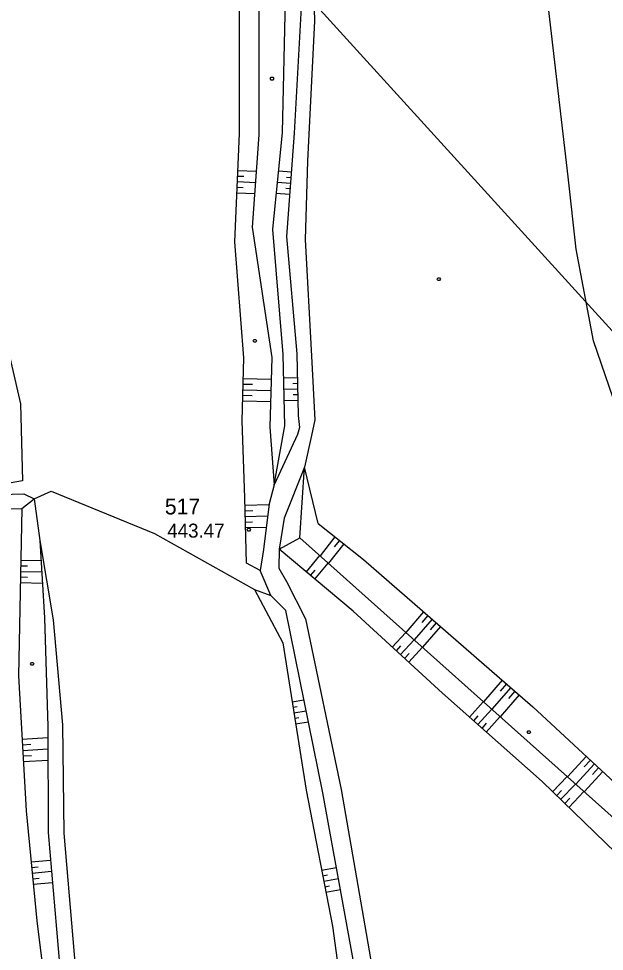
# Model space of a CAD drawing. Extents: x -664960 to -662754, y -993849 to -991145.
# Drawn here: x -663855.3 to -663729.8, y -993173.7 to -992973.8 of the extents above; entities that cross this region are included whole.
import ezdxf

# ---------------------------------------------------------------- set-up
doc = ezdxf.new("R2010")
doc.units = 0
for name, color, linetype in [('Vrstva 1', 7, 'Continuous'), ('Vrstva 13', 7, 'Continuous'), ('Vrstva 27', 7, 'Continuous'), ('Vrstva 57', 7, 'Continuous'), ('Vrstva 63', 7, 'Continuous'), ('Vrstva 8', 7, 'Continuous')]:
    doc.layers.add(name, color=color, linetype=linetype)

msp = doc.modelspace()

# ---------------------------------------------------------------- linework, layer by layer
at = {"layer": 'Vrstva 13'}
for points in [[(-663800.828, -992986.314), (-663800.648, -992986.614), (-663800.828, -992986.914), (-663801.188, -992986.914), (-663801.368, -992986.614), (-663801.188, -992986.314), (-663800.828, -992986.314)], [(-663765.08, -993029.301), (-663764.9, -993029.601), (-663765.08, -993029.901), (-663765.44, -993029.901), (-663765.62, -993029.601), (-663765.44, -993029.301), (-663765.08, -993029.301)], [(-663804.509, -993042.536), (-663804.329, -993042.836), (-663804.509, -993043.136), (-663804.869, -993043.136), (-663805.049, -993042.836), (-663804.869, -993042.536), (-663804.509, -993042.536)], [(-663852.233, -993111.799), (-663852.053, -993112.099), (-663852.233, -993112.399), (-663852.593, -993112.399), (-663852.773, -993112.099), (-663852.593, -993111.799), (-663852.233, -993111.799)], [(-663745.745, -993126.418), (-663745.565, -993126.718), (-663745.745, -993127.018), (-663746.105, -993127.018), (-663746.285, -993126.718), (-663746.105, -993126.418), (-663745.745, -993126.418)]]:
    msp.add_lwpolyline(points, dxfattribs=at)
at = {"layer": 'Vrstva 27'}
msp.add_line((-663804.75, -993096.16), (-663801.24, -993097.47), dxfattribs=at)
for points in [[(-663798.66, -992907.21), (-663803.28, -992878.12), (-663800.21, -992877.55), (-663794.6, -992912.25), (-663792.62, -992948.5), (-663791.93, -992974.25), (-663793.37, -993004.29), (-663793.87, -993021.14), (-663792.51, -993046.15), (-663791.85, -993059.78), (-663792.52, -993063.11), (-663794.05, -993069.95), (-663798.39, -993080.84), (-663799.49, -993087.48), (-663799.56, -993091.56)], [(-663798.66, -992907.21), (-663796.38, -992936.7), (-663794.84, -992972.55), (-663796.22, -992998.34), (-663797.91, -993020.49), (-663795.68, -993045.6), (-663795.37, -993058.81), (-663795.1, -993061.42), (-663795.54, -993062.92), (-663800.56, -993073.72), (-663801.6, -993077.75), (-663802.8, -993087.56), (-663803.57, -993092.11)], [(-663850.76, -993085.62), (-663849.8, -993102.26), (-663849.04, -993125.53), (-663849.03, -993148.28), (-663846.5, -993177.24), (-663842.24, -993200.89), (-663833.38, -993228.59), (-663823.87, -993255.25), (-663817.2, -993274.88), (-663813.34, -993284.73), (-663801.76, -993299.65)], [(-663850.76, -993085.62), (-663847.9, -993102.66), (-663845.89, -993125.16), (-663845.65, -993148.43), (-663843.14, -993177.79), (-663839.75, -993198.46), (-663830.82, -993226.75), (-663821.82, -993253.84), (-663814.3, -993276.27), (-663807.96, -993288.1), (-663798.2, -993300.61)], [(-663566.277, -993492.747), (-663573.405, -993481.951), (-663582.75, -993464.98), (-663590.11, -993455.44), (-663603.05, -993446.17), (-663622.25, -993432.96), (-663645.5, -993416.15), (-663669.59, -993394.5), (-663684.5, -993376.48), (-663705.06, -993341.62), (-663719.09, -993320.53), (-663726.89, -993308.98), (-663732.46, -993301.67), (-663748.35, -993282.31), (-663755.36, -993267.18), (-663772.33, -993222.31), (-663780.37, -993193.12), (-663790.1, -993139.75), (-663798.05, -993100.64), (-663801.24, -993097.47), (-663803.57, -993092.11)], [(-663799.56, -993091.56), (-663797.87, -993094.45), (-663793.81, -993102.42), (-663786.19, -993139.05), (-663776.88, -993192.57), (-663768.94, -993221.33), (-663752.26, -993266.73), (-663745.33, -993280.34), (-663730.13, -993299.39), (-663724.15, -993307.36), (-663716.72, -993318.58), (-663702.35, -993340.18), (-663681.94, -993374.67), (-663667.01, -993392.3), (-663643.69, -993413.59), (-663620.3, -993430.55), (-663600.52, -993442.61), (-663587.6, -993453.58), (-663580.01, -993463.19), (-663569.843, -993479.941), (-663562.861, -993490.76)]]:
    msp.add_lwpolyline(points, dxfattribs=at)
at = {"layer": 'Vrstva 57'}
msp.add_lwpolyline([(-663998.65, -992779.1), (-663970.58, -992774.57), (-663926.29, -992822.75), (-663869.96, -992884.99), (-663795.03, -992967.03), (-663725.94, -993043.04), (-663662.36, -993113.13), (-663592.02, -993190.94), (-663529.08, -993259.82), (-663458.89, -993337.24), (-663418.62, -993381.56)], dxfattribs=at)
at = {"layer": 'Vrstva 63'}
for p, q in [((-663808.3, -993006.301), (-663804.402, -993006.469)), ((-663796.856, -993006.677), (-663799.596, -993006.468)), ((-663808.352, -993007.5), (-663807.065, -993007.556)), ((-663796.947, -993007.873), (-663797.87, -993007.803)), ((-663808.456, -993009.898), (-663807.19, -993009.952)), ((-663808.404, -993008.699), (-663804.571, -993008.864)), ((-663797.039, -993009.07), (-663799.838, -993008.856)), ((-663797.13, -993010.266), (-663798.072, -993010.194)), ((-663808.507, -993011.097), (-663804.741, -993011.259)), ((-663797.221, -993011.463), (-663800.08, -993011.245)), ((-663807.198, -993052.103), (-663805.202, -993052.152)), ((-663807.169, -993050.904), (-663801.163, -993051.05)), ((-663795.558, -993050.795), (-663798.51, -993050.864)), ((-663795.53, -993051.995), (-663796.513, -993052.018)), ((-663807.257, -993054.503), (-663805.267, -993054.551)), ((-663807.227, -993053.303), (-663801.242, -993053.449)), ((-663795.502, -993053.195), (-663798.454, -993053.264)), ((-663795.474, -993054.394), (-663796.457, -993054.417)), ((-663807.286, -993055.702), (-663801.321, -993055.848)), ((-663795.445, -993055.594), (-663798.397, -993055.663)), ((-663791.11, -993082), (-663794.05, -993069.95)), ((-663852.02, -993076.68), (-663850.76, -993085.62)), ((-663806.807, -993078.09), (-663801.628, -993077.954)), ((-663801.54, -993077.54), (-663801.54, -993077.54)), ((-663806.776, -993079.29), (-663805.116, -993079.246)), ((-663806.744, -993080.489), (-663801.958, -993080.363)), ((-663806.712, -993081.689), (-663805.184, -993081.649)), ((-663806.681, -993082.889), (-663802.289, -993082.773)), ((-663787.503, -993084.872), (-663790.717, -993088.908)), ((-663785.625, -993086.367), (-663788.924, -993090.51)), ((-663786.564, -993085.62), (-663787.648, -993086.982)), ((-663854.872, -993089.864), (-663850.51, -993089.955)), ((-663793.646, -993092.37), (-663790.735, -993088.892)), ((-663791.805, -993093.911), (-663788.945, -993090.492)), ((-663854.922, -993092.263), (-663850.371, -993092.358)), ((-663854.897, -993091.063), (-663853.413, -993091.094)), ((-663792.725, -993093.141), (-663791.765, -993091.992)), ((-663854.947, -993093.463), (-663853.4, -993093.495)), ((-663854.972, -993094.662), (-663850.233, -993094.762)), ((-663768.509, -993100.937), (-663772.334, -993105.337)), ((-663766.697, -993102.511), (-663770.544, -993106.936)), ((-663767.603, -993101.724), (-663768.88, -993103.193)), ((-663764.886, -993104.085), (-663768.754, -993108.536)), ((-663765.792, -993103.298), (-663767.076, -993104.776)), ((-663775.225, -993108.48), (-663772.334, -993105.336)), ((-663774.342, -993109.292), (-663773.375, -993108.241)), ((-663773.458, -993110.104), (-663770.544, -993106.936)), ((-663771.692, -993111.729), (-663768.755, -993108.535)), ((-663772.575, -993110.917), (-663771.601, -993109.857)), ((-663751.644, -993115.596), (-663755.67, -993120.228)), ((-663750.738, -993116.383), (-663752.082, -993117.93)), ((-663749.832, -993117.17), (-663753.88, -993121.828)), ((-663748.927, -993117.958), (-663750.278, -993119.513)), ((-663796.682, -993120.205), (-663794.153, -993119.81)), ((-663758.659, -993123.531), (-663755.701, -993120.201)), ((-663748.021, -993118.745), (-663752.091, -993123.427)), ((-663796.497, -993121.391), (-663795.637, -993121.256)), ((-663796.311, -993122.576), (-663793.675, -993122.164)), ((-663756.864, -993125.125), (-663753.911, -993121.8)), ((-663796.126, -993123.762), (-663795.23, -993123.622)), ((-663795.941, -993124.947), (-663793.196, -993124.518)), ((-663757.761, -993124.328), (-663756.777, -993123.22)), ((-663755.07, -993126.718), (-663752.122, -993123.399)), ((-663755.967, -993125.922), (-663754.985, -993124.815)), ((-663854.592, -993128.24), (-663849.039, -993127.915)), ((-663854.522, -993129.438), (-663852.696, -993129.331)), ((-663854.451, -993130.636), (-663849.038, -993130.319)), ((-663854.381, -993131.834), (-663852.602, -993131.73)), ((-663733.624, -993131.925), (-663737.684, -993136.302)), ((-663854.311, -993133.032), (-663849.037, -993132.723)), ((-663731.865, -993133.557), (-663735.894, -993137.901)), ((-663732.745, -993132.741), (-663734.091, -993134.193)), ((-663730.985, -993134.373), (-663732.322, -993135.814)), ((-663740.85, -993139.524), (-663737.712, -993136.277)), ((-663730.105, -993135.189), (-663734.104, -993139.501)), ((-663739.125, -993141.192), (-663735.921, -993137.877)), ((-663739.987, -993140.358), (-663738.931, -993139.265)), ((-663737.399, -993142.86), (-663734.13, -993139.478)), ((-663738.262, -993142.026), (-663737.184, -993140.911)), ((-663852.653, -993154.575), (-663848.514, -993154.183)), ((-663852.541, -993155.769), (-663851.165, -993155.639)), ((-663852.428, -993156.964), (-663848.305, -993156.574)), ((-663790.385, -993156.358), (-663787.185, -993155.738)), ((-663852.315, -993158.159), (-663850.945, -993158.029)), ((-663790.157, -993157.536), (-663789.096, -993157.331)), ((-663789.928, -993158.714), (-663786.755, -993158.099)), ((-663852.202, -993159.353), (-663848.097, -993158.965)), ((-663789.7, -993159.892), (-663788.648, -993159.688)), ((-663789.472, -993161.071), (-663786.324, -993160.46))]:
    msp.add_line(p, q, dxfattribs=at)
for points in [[(-663803.57, -993092.11), (-663806.48, -993090.5), (-663806.85, -993076.47), (-663807.39, -993059.97), (-663807.06, -993046.45), (-663808.96, -993021.59), (-663807.96, -992998.41), (-663807.99, -992966.75), (-663808.62, -992935.63), (-663810.18, -992908.75), (-663815.86, -992880.07), (-663824.59, -992849.12), (-663829.13, -992816.83), (-663835.46, -992781.67), (-663839.851, -992756.951)], [(-663703.12, -993141.55), (-663703.33, -993135.57), (-663706.44, -993107.61), (-663711.52, -993089.56), (-663718.92, -993074.62), (-663727.02, -993057.64), (-663732.05, -993042.86), (-663735.81, -993023.2), (-663737.53, -993007.67), (-663742.14, -992967.66), (-663747.72, -992923.84), (-663786.36, -992914.44), (-663794.6, -992912.25)], [(-663803.84, -992971.94), (-663803.85, -992998.65), (-663805.25, -993018.47), (-663801.01, -993046.38), (-663801.5, -993061.31), (-663800.56, -993073.72), (-663798.27, -993061.07), (-663798.63, -993045.77), (-663800.86, -993018.93), (-663798.75, -992998.13), (-663798.09, -992969.67)], [(-663953.96, -992976.6), (-663944.14, -992978), (-663916.87, -992989.68), (-663873.66, -993007.23), (-663861.96, -993010.62), (-663860.36, -993033.02), (-663854.94, -993056.31), (-663854.48, -993072.82), (-663862.23, -993074.18), (-663868.63, -993079.01), (-663886.15, -993085.85), (-663925.46, -993100.87), (-663931.37, -993104)], [(-663799.49, -993087.48), (-663795.01, -993085.07), (-663794.05, -993069.95)], [(-663861.8, -993075.87), (-663854.19, -993075.63), (-663852.02, -993076.68)], [(-663854.64, -993078.78), (-663852.02, -993076.68), (-663848.36, -993075.04), (-663826.22, -993084.12), (-663804.75, -993096.16), (-663798.66, -993107.56), (-663793.71, -993139.21), (-663788.07, -993168.3), (-663784.47, -993194.39), (-663778.76, -993216.39), (-663771.46, -993242.85), (-663757.01, -993284.9), (-663749.83, -993296.15)], [(-663868.63, -993079.01), (-663854.64, -993078.78), (-663855.39, -993114.64), (-663853.69, -993143.61), (-663851.46, -993167.2), (-663846.95, -993203.4), (-663845.58, -993214.39), (-663841.42, -993235.66), (-663830.04, -993262.03), (-663819.16, -993294.58), (-663811.5, -993316.83), (-663809.19, -993328.03), (-663814.43, -993335.77), (-663815.62, -993345.98), (-663811.8, -993376.39), (-663812.8, -993389.09), (-663813.91, -993393.53), (-663818.11, -993403.98), (-663819.75, -993405.36)], [(-663791.11, -993082), (-663781.39, -993089.74), (-663745.07, -993121.31), (-663717.8, -993146.6), (-663703.82, -993161.01), (-663693.24, -993173.66), (-663687.18, -993183.2), (-663677.59, -993199.75), (-663676.28, -993214.64), (-663685.13, -993205.28), (-663693.35, -993191.46), (-663701.15, -993179.91), (-663722.82, -993156.95), (-663743.11, -993137.34), (-663764.47, -993118.37), (-663783.62, -993100.76), (-663799.49, -993087.48)], [(-663795.014, -993085.068), (-663727.66, -993145.26), (-663701.14, -993172.9), (-663688.74, -993188.73), (-663676.28, -993214.64)]]:
    msp.add_lwpolyline(points, dxfattribs=at)
at = {"layer": 'Vrstva 8'}
msp.add_lwpolyline([(-663805.81, -993083.01), (-663805.63, -993083.31), (-663805.81, -993083.61), (-663806.17, -993083.61), (-663806.35, -993083.31), (-663806.17, -993083.01), (-663805.81, -993083.01)], dxfattribs=at)

# ---------------------------------------------------------------- texts
at = {"layer": 'Vrstva 1'}
msp.add_text('517', height=3.4, dxfattribs=at).set_placement((-663823.984, -993080.049))
at = {"layer": 'Vrstva 63'}
msp.add_text('443.47', height=3, dxfattribs=at).set_placement((-663823.46, -993085.029))

doc.saveas('drawing.dxf')
